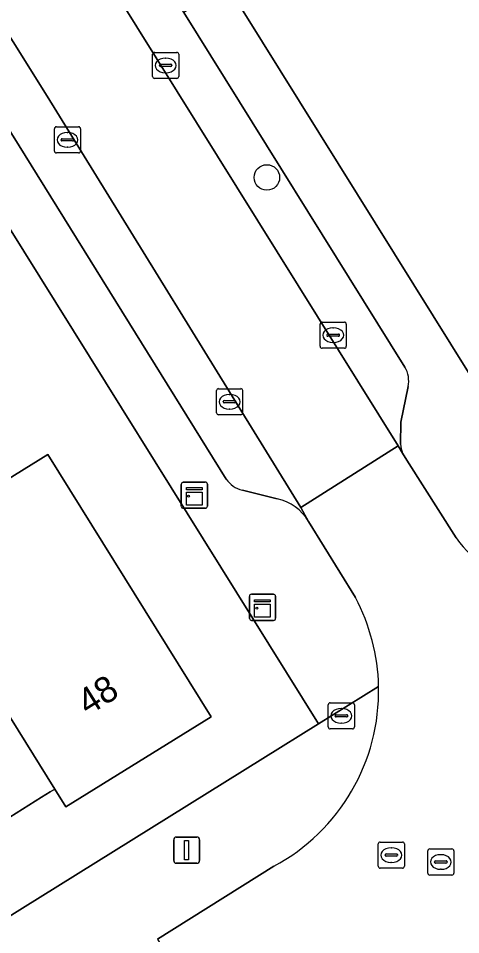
# Model space of a CAD drawing. Extents: x 159664 to 160323, y 385312 to 386115.
# Drawn here: x 160009.58 to 160026.52, y 385585.55 to 385620.61 of the extents above; entities that cross this region are included whole.
import ezdxf

# ---------------------------------------------------------------- set-up
doc = ezdxf.new("R2010")
doc.units = 0
for name, color, linetype in [('IMGEO_Boom', 7, 'Continuous'), ('IMGEO_Brandkraan', 7, 'Continuous'), ('IMGEO_Erf', 7, 'Continuous'), ('IMGEO_Kast', 7, 'Continuous'), ('IMGEO_Kolk', 7, 'Continuous'), ('IMGEO_Lichtmast', 7, 'Continuous'), ('IMGEO_Pand', 7, 'Continuous'), ('IMGEO_Pand_nummerreeks', 7, 'Continuous'), ('IMGEO_Parkeervlak_open', 7, 'Continuous'), ('IMGEO_Rijbaan_lokaal_open', 7, 'Continuous'), ('IMGEO_Rioolput', 7, 'Continuous'), ('IMGEO_Voetpad_open', 7, 'Continuous')]:
    doc.layers.add(name, color=color, linetype=linetype)

msp = doc.modelspace()

# ---------------------------------------------------------------- linework, layer by layer
at = {"layer": 'IMGEO_Boom'}
msp.add_circle((160019.101, 385614.519), 0.489, dxfattribs=at)
at = {"layer": 'IMGEO_Brandkraan'}
for p, q in [((160021.528, 385594.418), (160022.38, 385594.418)), ((160021.453, 385593.492), (160021.453, 385594.344)), ((160021.941, 385594.198), (160021.966, 385594.198)), ((160022.454, 385594.344), (160022.454, 385593.492)), ((160021.712, 385593.912), (160021.712, 385593.924)), ((160022.15, 385593.875), (160021.752, 385593.875)), ((160021.755, 385593.961), (160022.153, 385593.961)), ((160022.196, 385593.924), (160022.196, 385593.912)), ((160022.38, 385593.418), (160021.528, 385593.418)), ((160021.964, 385593.638), (160021.939, 385593.638))]:
    msp.add_line(p, q, dxfattribs=at)
for points in [[(160021.528, 385594.418), (160022.38, 385594.418)], [(160021.453, 385593.492), (160021.453, 385594.344)], [(160022.454, 385594.344), (160022.454, 385593.492)], [(160022.38, 385593.418), (160021.528, 385593.418)]]:
    msp.add_lwpolyline(points, dxfattribs=at)
for centre, radius, start, end in [((160021.53, 385594.342), 0.0765, 91.552, 178.448), ((160021.53, 385594.342), 0.0765, 91.552, 178.448), ((160022.378, 385594.342), 0.0765, 1.552, 88.448), ((160022.378, 385594.342), 0.0765, 1.552, 88.448), ((160021.752, 385593.921), 0.0403, 85.8775, 175.7526), ((160021.749, 385593.911), 0.0366, 178.938, 274.7102), ((160022.153, 385593.918), 0.043, 264.8664, 352.4533), ((160022.157, 385593.923), 0.0386, 1.7309, 96.639), ((160021.53, 385593.494), 0.0765, 181.552, 268.448), ((160021.53, 385593.494), 0.0765, 181.552, 268.448), ((160022.378, 385593.494), 0.0765, 271.552, 358.448), ((160022.378, 385593.494), 0.0765, 271.552, 358.448)]:
    msp.add_arc(centre, radius, start, end, dxfattribs=at)
for centre, major_axis, ratio, start_param, end_param in [((160021.94, 385593.918), (-0.387, 0.002), 0.722429, 4.712389, 7.853982), ((160021.965, 385593.918), (-0.39, 0.002), 0.717154, 1.570796, 4.712389)]:
    msp.add_ellipse(centre, major_axis=major_axis, ratio=ratio, start_param=start_param, end_param=end_param, dxfattribs=at)
at = {"layer": 'IMGEO_Erf'}
for points in [[(160034.995, 385633.443), (160026.316, 385627.843), (160026.297, 385626.311), (160026.134, 385626.195), (160024.632, 385626.557), (160023.091, 385625.594), (160024.863, 385622.758), (160022.205, 385621.111), (160020.433, 385623.947), (160017.449, 385622.082), (160031.258, 385599.938)], [(159972.712, 385563.525), (160021.079, 385593.612), (160007.265, 385615.734), (160004.443, 385613.972), (160006.212, 385611.118), (160003.546, 385609.465), (160001.777, 385612.318), (159999.866, 385611.132), (160000.024, 385609.18), (159999.624, 385608.955), (159997.547, 385610.093), (159988.972, 385604.606), (159989.111, 385602.797), (159988.808, 385602.612), (159987.078, 385603.403), (159978.302, 385597.897), (159978.493, 385596.005), (159978.125, 385595.774), (159976.162, 385596.621)], [(160006.869, 385601.543), (160010.713, 385603.916), (160016.971, 385593.886), (160011.402, 385590.438), (160010.975, 385591.119), (160010.808, 385591.015), (160010.465, 385590.801), (160008.513, 385589.584)]]:
    msp.add_lwpolyline(points, dxfattribs=at)
at = {"layer": 'IMGEO_Kast'}
for p, q in [((160015.823, 385601.935), (160015.823, 385602.776)), ((160015.823, 385602.776), (160015.823, 385601.935)), ((160015.898, 385602.86), (160016.739, 385602.86)), ((160016.739, 385602.86), (160015.898, 385602.86)), ((160016.823, 385602.785), (160016.823, 385601.944)), ((160016.823, 385601.944), (160016.823, 385602.785)), ((160016.748, 385601.86), (160015.907, 385601.86)), ((160015.907, 385601.86), (160016.748, 385601.86)), ((160018.509, 385598.571), (160019.35, 385598.571)), ((160019.35, 385598.571), (160018.509, 385598.571)), ((160018.434, 385597.646), (160018.434, 385598.487)), ((160018.434, 385598.487), (160018.434, 385597.646)), ((160019.434, 385598.496), (160019.434, 385597.655)), ((160019.434, 385597.655), (160019.434, 385598.496)), ((160019.359, 385597.571), (160018.518, 385597.571)), ((160018.518, 385597.571), (160019.359, 385597.571))]:
    msp.add_line(p, q, dxfattribs=at)
for points in [[(160016.018, 385602.65), (160016.618, 385602.65), (160016.618, 385602.565), (160016.018, 385602.565), (160016.018, 385602.65)], [(160016.018, 385602.475), (160016.618, 385602.475), (160016.618, 385601.986), (160016.018, 385601.986), (160016.018, 385602.475)], [(160018.629, 385598.361), (160019.229, 385598.361), (160019.229, 385598.276), (160018.629, 385598.276), (160018.629, 385598.361)], [(160018.629, 385598.186), (160019.229, 385598.186), (160019.229, 385597.697), (160018.629, 385597.697), (160018.629, 385598.186)]]:
    msp.add_lwpolyline(points, dxfattribs=at)
for centre in [(160016.102, 385602.324), (160018.713, 385598.035)]:
    msp.add_circle(centre, 0.0377, dxfattribs=at)
for centre, start, end in [((160015.901, 385602.782), 92.4484, 184.2845), ((160015.901, 385602.782), 92.4484, 184.2845), ((160016.745, 385602.782), 2.4484, 94.2845), ((160016.745, 385602.782), 2.4484, 94.2845), ((160015.901, 385601.938), 182.4484, 274.2845), ((160015.901, 385601.938), 182.4484, 274.2845), ((160016.745, 385601.938), 272.4484, 4.2845), ((160016.745, 385601.938), 272.4484, 4.2845), ((160018.512, 385598.493), 92.4484, 184.2845), ((160018.512, 385598.493), 92.4484, 184.2845), ((160019.356, 385598.493), 2.4484, 94.2845), ((160019.356, 385598.493), 2.4484, 94.2845), ((160018.512, 385597.649), 182.4484, 274.2845), ((160018.512, 385597.649), 182.4484, 274.2845), ((160019.356, 385597.649), 272.4484, 4.2845), ((160019.356, 385597.649), 272.4484, 4.2845)]:
    msp.add_arc(centre, 0.0779, start, end, dxfattribs=at)
at = {"layer": 'IMGEO_Kolk'}
for p, q in [((160014.799, 385619.306), (160015.651, 385619.306)), ((160014.724, 385618.38), (160014.724, 385619.232)), ((160015.212, 385619.086), (160015.237, 385619.086)), ((160015.725, 385619.232), (160015.725, 385618.38)), ((160014.983, 385618.8), (160014.983, 385618.812)), ((160015.421, 385618.763), (160015.023, 385618.763)), ((160015.026, 385618.849), (160015.424, 385618.849)), ((160015.467, 385618.812), (160015.467, 385618.8)), ((160015.651, 385618.306), (160014.799, 385618.306)), ((160015.235, 385618.526), (160015.21, 385618.526)), ((160011.039, 385616.457), (160011.891, 385616.457)), ((160010.964, 385615.531), (160010.964, 385616.383)), ((160011.452, 385616.237), (160011.477, 385616.237)), ((160011.965, 385616.383), (160011.965, 385615.531)), ((160011.223, 385615.951), (160011.223, 385615.963)), ((160011.661, 385615.914), (160011.263, 385615.914)), ((160011.266, 385616), (160011.664, 385616)), ((160011.707, 385615.963), (160011.707, 385615.951)), ((160011.891, 385615.457), (160011.039, 385615.457)), ((160011.475, 385615.677), (160011.45, 385615.677)), ((160021.14, 385608.058), (160021.14, 385608.91)), ((160021.215, 385608.984), (160022.067, 385608.984)), ((160021.628, 385608.764), (160021.653, 385608.764)), ((160022.141, 385608.91), (160022.141, 385608.058)), ((160021.399, 385608.478), (160021.399, 385608.49)), ((160021.837, 385608.441), (160021.439, 385608.441)), ((160021.442, 385608.527), (160021.84, 385608.527)), ((160021.883, 385608.49), (160021.883, 385608.478)), ((160021.651, 385608.204), (160021.626, 385608.204)), ((160022.067, 385607.984), (160021.215, 385607.984)), ((160017.172, 385605.511), (160017.172, 385606.363)), ((160017.247, 385606.437), (160018.099, 385606.437)), ((160018.173, 385606.363), (160018.173, 385605.511)), ((160017.431, 385605.931), (160017.431, 385605.943)), ((160017.474, 385605.98), (160017.872, 385605.98)), ((160017.66, 385606.217), (160017.685, 385606.217)), ((160017.915, 385605.943), (160017.915, 385605.931)), ((160017.869, 385605.894), (160017.471, 385605.894)), ((160017.683, 385605.657), (160017.658, 385605.657)), ((160018.099, 385605.437), (160017.247, 385605.437))]:
    msp.add_line(p, q, dxfattribs=at)
for points in [[(160014.799, 385619.306), (160015.651, 385619.306)], [(160014.724, 385618.38), (160014.724, 385619.232)], [(160015.725, 385619.232), (160015.725, 385618.38)], [(160015.651, 385618.306), (160014.799, 385618.306)], [(160011.039, 385616.457), (160011.891, 385616.457)], [(160010.964, 385615.531), (160010.964, 385616.383)], [(160011.965, 385616.383), (160011.965, 385615.531)], [(160011.891, 385615.457), (160011.039, 385615.457)], [(160021.14, 385608.058), (160021.14, 385608.91)], [(160021.215, 385608.984), (160022.067, 385608.984)], [(160022.141, 385608.91), (160022.141, 385608.058)], [(160022.067, 385607.984), (160021.215, 385607.984)], [(160017.172, 385605.511), (160017.172, 385606.363)], [(160017.247, 385606.437), (160018.099, 385606.437)], [(160018.173, 385606.363), (160018.173, 385605.511)], [(160018.099, 385605.437), (160017.247, 385605.437)]]:
    msp.add_lwpolyline(points, dxfattribs=at)
for centre, radius, start, end in [((160014.801, 385619.23), 0.0765, 91.552, 178.448), ((160014.801, 385619.23), 0.0765, 91.552, 178.448), ((160015.649, 385619.23), 0.0765, 1.552, 88.448), ((160015.649, 385619.23), 0.0765, 1.552, 88.448), ((160015.023, 385618.809), 0.0403, 85.8775, 175.7526), ((160015.02, 385618.799), 0.0366, 178.938, 274.7102), ((160015.424, 385618.806), 0.043, 264.8664, 352.4533), ((160015.428, 385618.811), 0.0386, 1.7309, 96.639), ((160014.801, 385618.382), 0.0765, 181.552, 268.448), ((160014.801, 385618.382), 0.0765, 181.552, 268.448), ((160015.649, 385618.382), 0.0765, 271.552, 358.448), ((160015.649, 385618.382), 0.0765, 271.552, 358.448), ((160011.041, 385616.381), 0.0765, 91.552, 178.448), ((160011.041, 385616.381), 0.0765, 91.552, 178.448), ((160011.889, 385616.381), 0.0765, 1.552, 88.448), ((160011.889, 385616.381), 0.0765, 1.552, 88.448), ((160011.263, 385615.96), 0.0403, 85.8775, 175.7526), ((160011.26, 385615.95), 0.0366, 178.938, 274.7102), ((160011.664, 385615.957), 0.043, 264.8664, 352.4533), ((160011.668, 385615.962), 0.0386, 1.7309, 96.639), ((160011.041, 385615.533), 0.0765, 181.552, 268.448), ((160011.041, 385615.533), 0.0765, 181.552, 268.448), ((160011.889, 385615.533), 0.0765, 271.552, 358.448), ((160011.889, 385615.533), 0.0765, 271.552, 358.448), ((160021.217, 385608.908), 0.0765, 91.552, 178.448), ((160021.217, 385608.908), 0.0765, 91.552, 178.448), ((160022.065, 385608.908), 0.0765, 1.552, 88.448), ((160022.065, 385608.908), 0.0765, 1.552, 88.448), ((160021.439, 385608.487), 0.0403, 85.8775, 175.7526), ((160021.436, 385608.477), 0.0366, 178.938, 274.7102), ((160021.84, 385608.484), 0.043, 264.8664, 352.4533), ((160021.844, 385608.489), 0.0386, 1.7309, 96.639), ((160021.217, 385608.06), 0.0765, 181.552, 268.448), ((160021.217, 385608.06), 0.0765, 181.552, 268.448), ((160022.065, 385608.06), 0.0765, 271.552, 358.448), ((160022.065, 385608.06), 0.0765, 271.552, 358.448), ((160017.249, 385606.361), 0.0765, 91.552, 178.448), ((160017.249, 385606.361), 0.0765, 91.552, 178.448), ((160018.097, 385606.361), 0.0765, 1.552, 88.448), ((160018.097, 385606.361), 0.0765, 1.552, 88.448), ((160017.471, 385605.94), 0.0403, 85.8775, 175.7526), ((160017.468, 385605.93), 0.0366, 178.938, 274.7102), ((160017.872, 385605.937), 0.043, 264.8664, 352.4533), ((160017.876, 385605.942), 0.0386, 1.7309, 96.639), ((160017.249, 385605.513), 0.0765, 181.552, 268.448), ((160017.249, 385605.513), 0.0765, 181.552, 268.448), ((160018.097, 385605.513), 0.0765, 271.552, 358.448), ((160018.097, 385605.513), 0.0765, 271.552, 358.448)]:
    msp.add_arc(centre, radius, start, end, dxfattribs=at)
for centre, major_axis, ratio, start_param, end_param in [((160015.211, 385618.806), (-0.387, 0.002), 0.722429, 4.712389, 7.853982), ((160015.236, 385618.806), (-0.39, 0.002), 0.717154, 1.570796, 4.712389), ((160011.451, 385615.957), (-0.387, 0.002), 0.722429, 4.712389, 7.853982), ((160011.476, 385615.957), (-0.39, 0.002), 0.717154, 1.570796, 4.712389), ((160021.627, 385608.484), (-0.387, 0.002), 0.722429, 4.712389, 7.853982), ((160021.652, 385608.484), (-0.39, 0.002), 0.717154, 1.570796, 4.712389), ((160017.659, 385605.937), (-0.387, 0.002), 0.722429, 4.712389, 7.853982), ((160017.684, 385605.937), (-0.39, 0.002), 0.717154, 1.570796, 4.712389)]:
    msp.add_ellipse(centre, major_axis=major_axis, ratio=ratio, start_param=start_param, end_param=end_param, dxfattribs=at)
at = {"layer": 'IMGEO_Lichtmast'}
for p, q in [((160015.532, 385588.379), (160015.532, 385589.179)), ((160015.532, 385589.179), (160015.532, 385588.379)), ((160015.632, 385589.279), (160016.422, 385589.279)), ((160016.422, 385589.279), (160015.632, 385589.279)), ((160016.522, 385589.179), (160016.522, 385588.379)), ((160016.522, 385588.379), (160016.522, 385589.179)), ((160016.422, 385588.279), (160015.632, 385588.279)), ((160015.632, 385588.279), (160016.422, 385588.279))]:
    msp.add_line(p, q, dxfattribs=at)
msp.add_lwpolyline([(160015.952, 385589.154), (160016.102, 385589.154), (160016.102, 385588.404), (160015.952, 385588.404), (160015.952, 385589.154)], dxfattribs=at)
for centre, start, end in [((160015.632, 385589.179), 90, 180), ((160015.632, 385589.179), 90, 180), ((160016.422, 385589.179), 0, 90), ((160016.422, 385589.179), 360, 90), ((160015.632, 385588.379), 180, 270), ((160015.632, 385588.379), 180, 270), ((160016.422, 385588.379), 270, 0), ((160016.422, 385588.379), 270, 0)]:
    msp.add_arc(centre, 0.1, start, end, dxfattribs=at)
at = {"layer": 'IMGEO_Pand'}
for points in [[(160010.713, 385603.916), (160006.869, 385601.543), (160007.664, 385600.271), (160005.94, 385599.193), (160010.975, 385591.119), (160011.402, 385590.438), (160016.971, 385593.886)], [(160005.94, 385599.193), (160004.213, 385598.113), (160003.418, 385599.385), (159999.827, 385597.14), (160000.621, 385595.867), (160005.653, 385587.799), (160005.849, 385587.921), (160006.288, 385587.217), (160008.952, 385588.88), (160008.513, 385589.584), (160010.465, 385590.801), (160010.808, 385591.015), (160010.975, 385591.119)]]:
    msp.add_lwpolyline(points, close=True, dxfattribs=at)
at = {"layer": 'IMGEO_Parkeervlak_open'}
for points in [[(159951.903, 385720.143), (159963.01, 385702.177), (159985.962, 385665.401), (159987.857, 385662.364), (160024.125, 385604.253), (160024.299, 385603.973)], [(160024.384, 385607.262), (160015.917, 385620.829), (160013.539, 385624.666), (159966.892, 385699.4), (159964.522, 385703.225), (159955.104, 385718.361)], [(160020.693, 385601.361), (160020.396, 385601.89), (160010.69, 385617.63), (159984.119, 385660.032), (159982.218, 385663.065), (159948.048, 385717.594)], [(159948.245, 385713.947), (159957.628, 385698.921), (159960.016, 385695.097), (160006.699, 385620.386), (160009.09, 385616.567), (160017.543, 385602.98)], [(160024.218, 385604.312), (160024.227, 385605.152), (160024.507, 385606.519)], [(160018.162, 385602.557), (160019.495, 385602.217)]]:
    msp.add_lwpolyline(points, dxfattribs=at)
for centre, radius, start, end in [((160023.544, 385606.741), 0.988, 347.0014, 31.7982), ((160025.241, 385604.377), 1.025, 183.6538, 203.2226), ((160018.366, 385603.52), 0.984, 213.2628, 258.0429), ((160019.131, 385600.441), 1.813, 30.49, 78.4166)]:
    msp.add_arc(centre, radius, start, end, dxfattribs=at)
at = {"layer": 'IMGEO_Rijbaan_lokaal_open'}
msp.add_lwpolyline([(160020.396, 385601.89), (160024.125, 385604.253), (159987.857, 385662.364), (159984.119, 385660.032), (160010.69, 385617.63)], close=True, dxfattribs=at)
for points in [[(160026.348, 385600.727), (160024.466, 385603.705), (160024.299, 385603.973), (160024.125, 385604.253), (160020.396, 385601.89), (160020.693, 385601.361), (160022.489, 385598.447)], [(160019.369, 385588.165), (160014.915, 385585.376), (160017.334, 385581.279), (160019.403, 385582.565)]]:
    msp.add_lwpolyline(points, dxfattribs=at)
for centre, radius, start, end in [((160032.549, 385605.413), 7.772, 217.0756, 242.5733), ((160015.755, 385594.868), 7.626, 1.3152, 27.9895), ((160015.769, 385594.872), 7.612, 298.2245, 1.2895)]:
    msp.add_arc(centre, radius, start, end, dxfattribs=at)
at = {"layer": 'IMGEO_Rioolput'}
for p, q in [((160023.441, 385589.09), (160024.293, 385589.09)), ((160023.366, 385588.164), (160023.366, 385589.016)), ((160023.854, 385588.87), (160023.879, 385588.87)), ((160024.367, 385589.016), (160024.367, 385588.164)), ((160025.261, 385587.901), (160025.261, 385588.753)), ((160025.336, 385588.827), (160026.188, 385588.827)), ((160026.262, 385588.753), (160026.262, 385587.901)), ((160023.625, 385588.584), (160023.625, 385588.596)), ((160024.063, 385588.547), (160023.665, 385588.547)), ((160023.668, 385588.633), (160024.066, 385588.633)), ((160024.109, 385588.596), (160024.109, 385588.584)), ((160025.749, 385588.607), (160025.774, 385588.607)), ((160024.293, 385588.09), (160023.441, 385588.09)), ((160023.877, 385588.31), (160023.852, 385588.31)), ((160025.52, 385588.321), (160025.52, 385588.333)), ((160025.958, 385588.284), (160025.56, 385588.284)), ((160025.563, 385588.37), (160025.961, 385588.37)), ((160025.772, 385588.047), (160025.747, 385588.047)), ((160026.004, 385588.333), (160026.004, 385588.321)), ((160026.188, 385587.827), (160025.336, 385587.827))]:
    msp.add_line(p, q, dxfattribs=at)
for points in [[(160023.441, 385589.09), (160024.293, 385589.09)], [(160023.366, 385588.164), (160023.366, 385589.016)], [(160024.367, 385589.016), (160024.367, 385588.164)], [(160025.261, 385587.901), (160025.261, 385588.753)], [(160025.336, 385588.827), (160026.188, 385588.827)], [(160026.262, 385588.753), (160026.262, 385587.901)], [(160024.293, 385588.09), (160023.441, 385588.09)], [(160026.188, 385587.827), (160025.336, 385587.827)]]:
    msp.add_lwpolyline(points, dxfattribs=at)
for centre, radius, start, end in [((160023.443, 385589.014), 0.0765, 91.552, 178.448), ((160023.443, 385589.014), 0.0765, 91.552, 178.448), ((160024.291, 385589.014), 0.0765, 1.552, 88.448), ((160024.291, 385589.014), 0.0765, 1.552, 88.448), ((160025.338, 385588.751), 0.0765, 91.552, 178.448), ((160025.338, 385588.751), 0.0765, 91.552, 178.448), ((160026.186, 385588.751), 0.0765, 1.552, 88.448), ((160026.186, 385588.751), 0.0765, 1.552, 88.448), ((160023.665, 385588.593), 0.0403, 85.8775, 175.7526), ((160023.662, 385588.583), 0.0366, 178.938, 274.7102), ((160024.066, 385588.59), 0.043, 264.8664, 352.4533), ((160024.07, 385588.595), 0.0386, 1.7309, 96.639), ((160023.443, 385588.166), 0.0765, 181.552, 268.448), ((160023.443, 385588.166), 0.0765, 181.552, 268.448), ((160024.291, 385588.166), 0.0765, 271.552, 358.448), ((160024.291, 385588.166), 0.0765, 271.552, 358.448), ((160025.56, 385588.33), 0.0403, 85.8775, 175.7526), ((160025.557, 385588.32), 0.0366, 178.938, 274.7102), ((160025.961, 385588.327), 0.043, 264.8664, 352.4533), ((160025.965, 385588.332), 0.0386, 1.7309, 96.639), ((160025.338, 385587.903), 0.0765, 181.552, 268.448), ((160025.338, 385587.903), 0.0765, 181.552, 268.448), ((160026.186, 385587.903), 0.0765, 271.552, 358.448), ((160026.186, 385587.903), 0.0765, 271.552, 358.448)]:
    msp.add_arc(centre, radius, start, end, dxfattribs=at)
for centre, major_axis, ratio, start_param, end_param in [((160023.853, 385588.59), (-0.387, 0.002), 0.722429, 4.712389, 7.853982), ((160023.878, 385588.59), (-0.39, 0.002), 0.717154, 1.570796, 4.712389), ((160025.748, 385588.327), (-0.387, 0.002), 0.722429, 4.712389, 7.853982), ((160025.773, 385588.327), (-0.39, 0.002), 0.717154, 1.570796, 4.712389)]:
    msp.add_ellipse(centre, major_axis=major_axis, ratio=ratio, start_param=start_param, end_param=end_param, dxfattribs=at)
at = {"layer": 'IMGEO_Voetpad_open'}
for points in [[(160028.969, 385598.514), (160031.258, 385599.938), (160017.449, 385622.082), (160015.328, 385625.483), (159968.406, 385700.726), (159966.312, 385704.084), (159951.602, 385727.673)], [(159943.501, 385722.607), (159941.362, 385721.273), (159956.019, 385697.802), (159958.233, 385694.255), (160005.148, 385619.125), (160007.265, 385615.734), (160021.079, 385593.612), (160023.379, 385595.043)], [(159955.104, 385718.361), (159964.522, 385703.225), (159964.896, 385703.465), (159967.266, 385699.641), (159966.892, 385699.4), (160013.539, 385624.666), (160013.922, 385624.884), (160016.29, 385621.068), (160015.917, 385620.829), (160024.384, 385607.262)], [(160017.543, 385602.98), (160009.09, 385616.567), (160008.706, 385616.33), (160006.332, 385620.147), (160006.699, 385620.386), (159960.016, 385695.097), (159959.64, 385694.86), (159957.242, 385698.687), (159957.628, 385698.921), (159948.245, 385713.947)], [(160024.507, 385606.519), (160024.227, 385605.152), (160024.218, 385604.312)], [(160024.299, 385603.973), (160024.466, 385603.705), (160026.348, 385600.727)], [(160019.495, 385602.217), (160018.162, 385602.557)], [(160022.489, 385598.447), (160020.693, 385601.361)], [(160023.379, 385595.043), (160021.079, 385593.612), (159972.712, 385563.525), (159970.609, 385562.217)], [(160014.915, 385585.376), (160019.369, 385588.165)]]:
    msp.add_lwpolyline(points, dxfattribs=at)
for centre, radius, start, end in [((160023.544, 385606.741), 0.988, 347.0014, 31.7982), ((160025.241, 385604.377), 1.025, 183.6538, 203.2226), ((160018.366, 385603.52), 0.984, 213.2628, 258.0429), ((160019.131, 385600.441), 1.813, 30.49, 78.4166), ((160032.549, 385605.413), 7.772, 217.0756, 242.5733), ((160015.755, 385594.868), 7.626, 1.3152, 27.9895), ((160015.769, 385594.872), 7.612, 298.2245, 1.2895)]:
    msp.add_arc(centre, radius, start, end, dxfattribs=at)

# ---------------------------------------------------------------- texts
at = {"layer": 'IMGEO_Pand_nummerreeks'}
msp.add_text('48', height=1, rotation=31.9768, dxfattribs=at).set_placement((160012.245, 385593.905))

doc.saveas('drawing.dxf')
